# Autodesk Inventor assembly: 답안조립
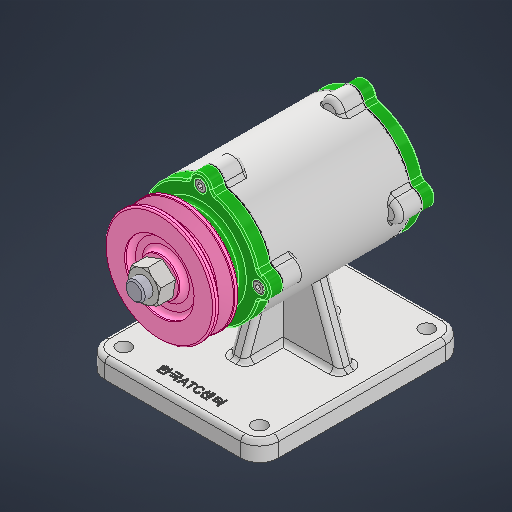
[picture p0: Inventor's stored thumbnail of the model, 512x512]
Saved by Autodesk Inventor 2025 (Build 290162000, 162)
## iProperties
Created: 2025-08
Part Number: 답안조립
Document SubType Name: Assembly
Designer: infra005
Author: infra005
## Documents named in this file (12)
- C:\Users\infra005\Desktop\750806V1019\답안조립.iam
- C:\Users\infra005\Desktop\750806V1019\본체.ipt
- C:\Users\infra005\Desktop\750806V1019\V-벨트풀리\V-벨트풀리.ipt
- C:\Users\infra005\Desktop\750806V1019\개스킷\개스킷.ipt
- C:\Users\infra005\Desktop\750806V1019\너트 M12 x 1.25\너트 M12 x 1.25.ipt
- C:\Users\infra005\Desktop\750806V1019\뒤커버\뒤커버.ipt
- C:\Users\infra005\Desktop\750806V1019\베어링 6204\베어링 6204.ipt
- C:\Users\infra005\Desktop\750806V1019\볼트 M4 x 12\볼트 M4 x 12.ipt
- C:\Users\infra005\Desktop\750806V1019\앞커버\앞커버.ipt
- C:\Users\infra005\Desktop\750806V1019\오일 실\오일 실.ipt
- C:\Users\infra005\Desktop\750806V1019\축\축.ipt
- C:\Users\infra005\Desktop\750806V1019\키 4 x 4\키 4 x 4.ipt
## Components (3 placed, 2 different names)
1. V-벨트풀리:1
2. 개스킷:1
3. 개스킷:2
